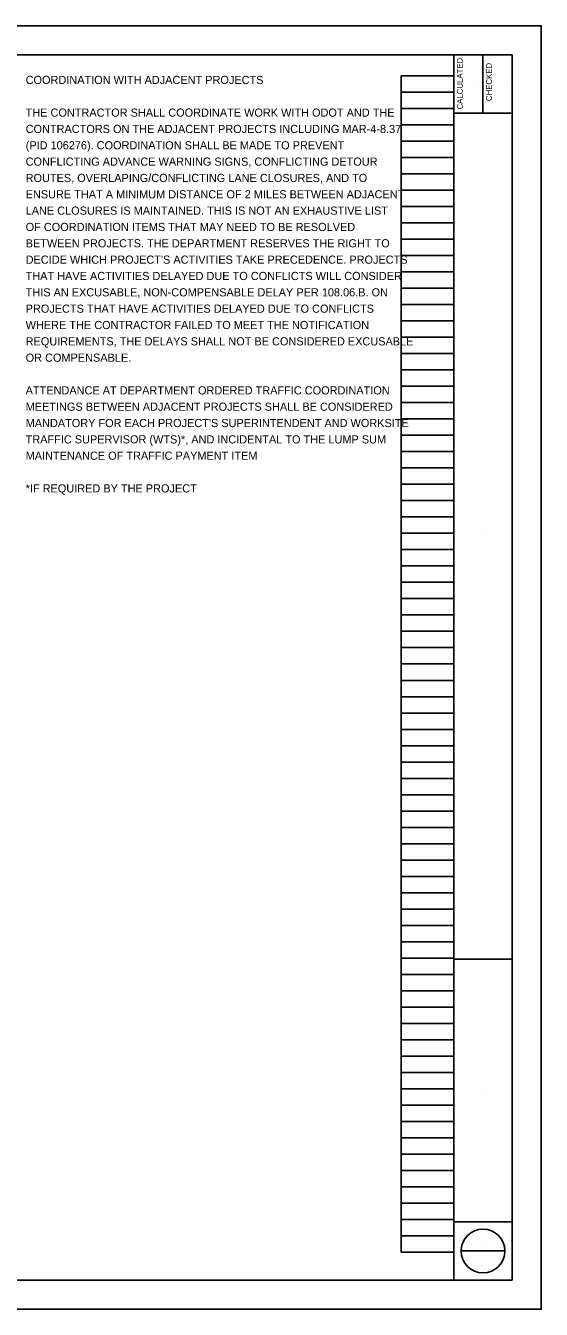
# Model space of a CAD drawing. Extents: x -12.2 to 34.1, y -24.5 to 43.2.
# Drawn here: x 25.16 to 34, y 0 to 22 of the extents above; entities that cross this region are included whole.
import ezdxf

# ---------------------------------------------------------------- set-up
doc = ezdxf.new("R2010")
doc.units = 0
for name, color, linetype in [('SH_Border', 7, 'Continuous'), ('SH_Cut_Line', 7, 'Continuous'), ('SH_Data', 7, 'Continuous'), ('SH_Text', 7, 'Continuous')]:
    doc.layers.add(name, color=color, linetype=linetype)

msp = doc.modelspace()

# ---------------------------------------------------------------- linework, layer by layer
at = {"layer": 'SH_Border'}
for p, q in [((32.5, 0.5), (32.5, 21.5)), ((33, 21.5), (33, 20.5)), ((32.5, 20.5), (33.5, 20.5)), ((32.5, 6), (33.5, 6)), ((32.5, 1.5), (33.5, 1.5))]:
    msp.add_line(p, q, dxfattribs=at)
msp.add_lwpolyline([(2, 21.5), (33.5, 21.5), (33.5, 0.5), (2, 0.5)], close=True, dxfattribs=at)
at = {"layer": 'SH_Cut_Line'}
msp.add_lwpolyline([(0, 0), (34, 0), (34, 22), (0, 22)], close=True, dxfattribs=at)
at = {"layer": 'SH_Data'}
for p, q in [((31.6, 0.98), (31.6, 21.14)), ((31.6, 21.14), (32.5, 21.14)), ((32.5, 0.98), (32.5, 21.14)), ((32.92, 21.004), (32.92, 21.004)), ((33.42, 21.004), (33.42, 21.004)), ((31.6, 20.86), (32.5, 20.86)), ((31.6, 20.58), (32.5, 20.58)), ((31.6, 20.3), (32.5, 20.3)), ((31.6, 20.02), (32.5, 20.02)), ((31.6, 19.74), (32.5, 19.74)), ((31.6, 19.46), (32.5, 19.46)), ((31.6, 19.18), (32.5, 19.18)), ((31.6, 18.9), (32.5, 18.9)), ((31.6, 18.62), (32.5, 18.62)), ((31.6, 18.34), (32.5, 18.34)), ((31.6, 18.06), (32.5, 18.06)), ((31.6, 17.78), (32.5, 17.78)), ((31.6, 17.5), (32.5, 17.5)), ((31.6, 17.22), (32.5, 17.22)), ((31.6, 16.94), (32.5, 16.94)), ((31.6, 16.66), (32.5, 16.66)), ((31.6, 16.38), (32.5, 16.38)), ((31.6, 16.1), (32.5, 16.1)), ((31.6, 15.82), (32.5, 15.82)), ((31.6, 15.54), (32.5, 15.54)), ((31.6, 15.26), (32.5, 15.26)), ((31.6, 14.98), (32.5, 14.98)), ((31.6, 14.7), (32.5, 14.7)), ((31.6, 14.42), (32.5, 14.42)), ((31.6, 14.14), (32.5, 14.14)), ((31.6, 13.86), (32.5, 13.86)), ((31.6, 13.58), (32.5, 13.58)), ((31.6, 13.3), (32.5, 13.3)), ((33, 13.292), (33, 13.292)), ((31.6, 13.02), (32.5, 13.02)), ((31.6, 12.74), (32.5, 12.74)), ((31.6, 12.46), (32.5, 12.46)), ((31.6, 12.18), (32.5, 12.18)), ((31.6, 11.9), (32.5, 11.9)), ((31.6, 11.62), (32.5, 11.62)), ((31.6, 11.34), (32.5, 11.34)), ((31.6, 11.06), (32.5, 11.06)), ((31.6, 10.78), (32.5, 10.78)), ((31.6, 10.5), (32.5, 10.5)), ((31.6, 10.22), (32.5, 10.22)), ((31.6, 9.94), (32.5, 9.94)), ((31.6, 9.66), (32.5, 9.66)), ((31.6, 9.38), (32.5, 9.38)), ((31.6, 9.1), (32.5, 9.1)), ((31.6, 8.82), (32.5, 8.82)), ((31.6, 8.54), (32.5, 8.54)), ((31.6, 8.26), (32.5, 8.26)), ((31.6, 7.98), (32.5, 7.98)), ((31.6, 7.7), (32.5, 7.7)), ((31.6, 7.42), (32.5, 7.42)), ((31.6, 7.14), (32.5, 7.14)), ((31.6, 6.86), (32.5, 6.86)), ((31.6, 6.58), (32.5, 6.58)), ((31.6, 6.3), (32.5, 6.3)), ((31.6, 6.02), (32.5, 6.02)), ((31.6, 5.74), (32.5, 5.74)), ((31.6, 5.46), (32.5, 5.46)), ((31.6, 5.18), (32.5, 5.18)), ((31.6, 4.9), (32.5, 4.9)), ((31.6, 4.62), (32.5, 4.62)), ((31.6, 4.34), (32.5, 4.34)), ((31.6, 4.06), (32.5, 4.06)), ((31.6, 3.78), (32.5, 3.78)), ((33, 3.792), (33, 3.792)), ((31.6, 3.5), (32.5, 3.5)), ((31.6, 3.22), (32.5, 3.22)), ((31.6, 2.94), (32.5, 2.94)), ((31.6, 2.66), (32.5, 2.66)), ((31.6, 2.38), (32.5, 2.38)), ((31.6, 2.1), (32.5, 2.1)), ((31.6, 1.82), (32.5, 1.82)), ((31.6, 1.54), (32.5, 1.54)), ((31.6, 1.26), (32.5, 1.26)), ((31.6, 0.98), (32.5, 0.98)), ((32.625, 1), (33.375, 1)), ((33, 1.085), (33, 1.085)), ((33, 0.745), (33, 0.745))]:
    msp.add_line(p, q, dxfattribs=at)
msp.add_circle((33, 1), 0.375, dxfattribs=at)

# ---------------------------------------------------------------- texts
for s, p in [('CALCULATED', (32.652, 20.565)), ('CHECKED', (33.152, 20.708))]:
    msp.add_text(s, height=0.1, rotation=90, dxfattribs=at).set_placement(p)
at = {"layer": 'SH_Text'}
for s, p in [('COORDINATION WITH ADJACENT PROJECTS', (25.16, 21)), ('THE CONTRACTOR SHALL COORDINATE WORK WITH ODOT AND THE ', (25.16, 20.44)), ('CONTRACTORS ON THE ADJACENT PROJECTS INCLUDING MAR-4-8.37 ', (25.16, 20.16)), ('(PID 106276). COORDINATION SHALL BE MADE TO PREVENT ', (25.16, 19.88)), ('CONFLICTING ADVANCE WARNING SIGNS, CONFLICTING DETOUR ', (25.16, 19.6)), ('ROUTES, OVERLAPING/CONFLICTING LANE CLOSURES, AND TO ', (25.16, 19.32)), ('ENSURE THAT A MINIMUM DISTANCE OF 2 MILES BETWEEN ADJACENT ', (25.16, 19.04)), ('LANE CLOSURES IS MAINTAINED. THIS IS NOT AN EXHAUSTIVE LIST ', (25.16, 18.76)), ('OF COORDINATION ITEMS THAT MAY NEED TO BE RESOLVED ', (25.16, 18.48)), ('BETWEEN PROJECTS. THE DEPARTMENT RESERVES THE RIGHT TO ', (25.16, 18.2)), ("DECIDE WHICH PROJECT'S ACTIVITIES TAKE PRECEDENCE. PROJECTS ", (25.16, 17.92)), ('THAT HAVE ACTIVITIES DELAYED DUE TO CONFLICTS WILL CONSIDER ', (25.16, 17.64)), ('THIS AN EXCUSABLE, NON-COMPENSABLE DELAY PER 108.06.B. ON ', (25.16, 17.36)), ('PROJECTS THAT HAVE ACTIVITIES DELAYED DUE TO CONFLICTS ', (25.16, 17.08)), ('WHERE THE CONTRACTOR FAILED TO MEET THE NOTIFICATION ', (25.16, 16.8)), ('REQUIREMENTS, THE DELAYS SHALL NOT BE CONSIDERED EXCUSABLE ', (25.16, 16.52)), ('OR COMPENSABLE.', (25.16, 16.24)), ('ATTENDANCE AT DEPARTMENT ORDERED TRAFFIC COORDINATION ', (25.16, 15.68)), ('MEETINGS BETWEEN ADJACENT PROJECTS SHALL BE CONSIDERED ', (25.16, 15.4)), ("MANDATORY FOR EACH PROJECT'S SUPERINTENDENT AND WORKSITE ", (25.16, 15.12)), ('TRAFFIC SUPERVISOR (WTS)*, AND INCIDENTAL TO THE LUMP SUM ', (25.16, 14.84)), ('MAINTENANCE OF TRAFFIC PAYMENT ITEM', (25.16, 14.56)), ('*IF REQUIRED BY THE PROJECT', (25.16, 14))]:
    msp.add_text(s, height=0.14, dxfattribs=at).set_placement(p)

doc.saveas('drawing.dxf')
